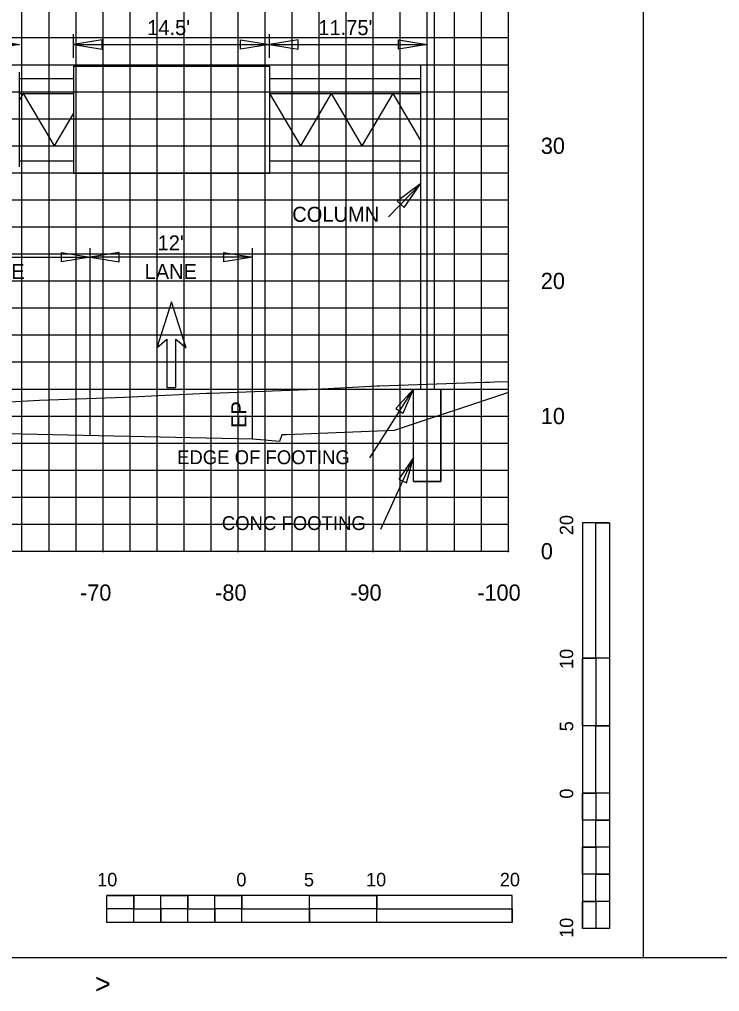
# Model space of a CAD drawing. Extents: x 2193008 to 2198143, y 1236112 to 1237864.
# Drawn here: x 2194986.7 to 2195038.5, y 1237225.5 to 1237297.5 of the extents above; entities that cross this region are included whole.
import ezdxf

# ---------------------------------------------------------------- set-up
doc = ezdxf.new("R2010")
doc.units = 0
for name, color, linetype in [('10', 7, 'Continuous'), ('3', 7, 'Continuous'), ('31', 7, 'Continuous'), ('60', 7, 'Continuous'), ('CL-CNST', 7, 'Continuous'), ('GSCOLORFILL', 7, 'Continuous'), ('GSDIMS', 7, 'Continuous'), ('Level 1', 7, 'Continuous'), ('Level 28', 7, 'Continuous'), ('Level 55', 7, 'Continuous'), ('Level 62', 7, 'Continuous'), ('M-ROADS', 7, 'Continuous'), ('V7Level1', 7, 'Continuous')]:
    doc.layers.add(name, color=color, linetype=linetype)

msp = doc.modelspace()

# ---------------------------------------------------------------- linework, layer by layer
msp.add_line((2195016.86, 1237292.389), (2195016.86, 1237297.403))
at = {"layer": '3'}
for p, q in [((2195032.86, 1237228.046), (2195032.86, 1237323.046)), ((2195017.36, 1237306.728), (2195017.36, 1237294.084)), ((2195016.36, 1237294.084), (2195016.36, 1237270.106)), ((2195017.36, 1237294.084), (2195017.36, 1237270.106)), ((2195013.991, 1237282.842), (2195016.36, 1237285.285)), ((2194991.918, 1237266.649), (2194991.918, 1237280.525)), ((2195003.918, 1237266.385), (2195003.918, 1237280.525)), ((2195012.608, 1237265.025), (2195015.836, 1237270.106)), ((2195015.836, 1237270.106), (2195017.86, 1237270.106)), ((2195015.836, 1237263.254), (2195015.836, 1237270.106)), ((2195017.86, 1237263.254), (2195017.86, 1237270.106)), ((2195013.41, 1237259.743), (2195015.836, 1237265.045)), ((2195015.836, 1237263.254), (2195017.86, 1237263.254)), ((2194882.86, 1237228.046), (2195182.86, 1237228.046))]:
    msp.add_line(p, q, dxfattribs=at)
at = {"layer": '60'}
for p, q in [((2195022.86, 1237258.106), (2195022.86, 1237318.106)), ((2195022.92, 1237288.106), (2195022.86, 1237288.106)), ((2195022.92, 1237278.106), (2195022.86, 1237278.106)), ((2195022.92, 1237268.106), (2195022.86, 1237268.106)), ((2194892.86, 1237258.106), (2195022.86, 1237258.106)), ((2194992.86, 1237258.046), (2194992.86, 1237258.106)), ((2195002.86, 1237258.046), (2195002.86, 1237258.106)), ((2195012.86, 1237258.046), (2195012.86, 1237258.106)), ((2195022.86, 1237258.046), (2195022.86, 1237258.106)), ((2195022.92, 1237258.106), (2195022.86, 1237258.106))]:
    msp.add_line(p, q, dxfattribs=at)
at = {"layer": 'CL-CNST'}
msp.add_lwpolyline([(2195022.86, 1237269.861), (2195014.414, 1237267.045), (2195010.113, 1237266.873), (2195006.414, 1237266.725), (2195006.088, 1237266.725), (2195006.085, 1237266.725), (2195005.918, 1237266.225), (2195004.805, 1237266.314), (2195003.918, 1237266.385), (2194951.493, 1237267.538), (2194950.59, 1237267.558), (2194949.493, 1237267.582), (2194949.323, 1237268.082), (2194948.993, 1237268.082), (2194943.692, 1237268.294), (2194938.236, 1237268.512), (2194935.061, 1237268.561), (2194927.574, 1237268.677)], dxfattribs=at)
at = {"layer": 'GSCOLORFILL'}
msp.add_line((2194986.672, 1237286.538), (2194986.672, 1237293.547), dxfattribs=at)
at = {"layer": 'GSDIMS'}
for p, q in [((2194990.664, 1237294.621), (2194990.664, 1237296.362)), ((2195005.172, 1237294.621), (2195005.172, 1237296.362)), ((2194956.664, 1237295.604), (2194986.672, 1237295.604)), ((2194990.664, 1237295.604), (2195005.172, 1237295.604)), ((2195005.172, 1237295.604), (2195016.86, 1237295.604)), ((2194990.664, 1237294.001), (2195005.172, 1237294.001)), ((2194990.664, 1237294.001), (2194990.664, 1237286.084)), ((2195005.172, 1237294.001), (2195005.172, 1237286.084)), ((2195016.36, 1237294.084), (2195017.36, 1237294.084)), ((2194986.672, 1237293.084), (2194990.664, 1237293.084)), ((2195005.172, 1237293.084), (2195016.36, 1237293.084)), ((2194986.96, 1237291.974), (2194986.672, 1237291.486)), ((2194986.672, 1237291.974), (2194990.664, 1237291.974)), ((2194986.96, 1237291.974), (2194989.238, 1237288.111)), ((2195005.188, 1237291.974), (2195005.172, 1237291.946)), ((2195005.172, 1237291.974), (2195016.36, 1237291.974)), ((2195005.188, 1237291.974), (2195007.467, 1237288.111)), ((2195009.745, 1237291.974), (2195007.467, 1237288.111)), ((2195009.745, 1237291.974), (2195012.024, 1237288.111)), ((2195014.303, 1237291.974), (2195012.024, 1237288.111)), ((2195014.303, 1237291.974), (2195016.36, 1237288.485)), ((2194990.664, 1237290.527), (2194989.238, 1237288.111)), ((2194986.672, 1237288.111), (2194990.664, 1237288.111)), ((2195005.172, 1237288.111), (2195016.36, 1237288.111)), ((2194986.672, 1237287.001), (2194990.664, 1237287.001)), ((2195005.172, 1237287.001), (2195016.36, 1237287.001)), ((2194990.664, 1237286.084), (2195005.172, 1237286.084)), ((2194978.418, 1237279.864), (2194991.918, 1237279.864)), ((2195003.918, 1237279.863), (2194991.918, 1237279.863))]:
    msp.add_line(p, q, dxfattribs=at)
for points in [[(2194986.672, 1237295.604), (2194984.544, 1237295.257), (2194984.544, 1237295.952)], [(2194990.664, 1237295.604), (2194992.792, 1237295.257), (2194992.792, 1237295.952)], [(2195005.172, 1237295.604), (2195003.044, 1237295.257), (2195003.044, 1237295.952)], [(2195005.172, 1237295.604), (2195007.301, 1237295.257), (2195007.301, 1237295.952)], [(2195016.86, 1237295.604), (2195014.732, 1237295.257), (2195014.732, 1237295.952)], [(2195016.36, 1237285.285), (2195014.638, 1237284.014), (2195015.152, 1237283.535)], [(2194991.918, 1237279.864), (2194989.79, 1237279.517), (2194989.79, 1237280.211)], [(2194991.918, 1237279.863), (2194994.046, 1237279.516), (2194994.046, 1237280.21)], [(2195003.918, 1237279.863), (2195001.79, 1237279.516), (2195001.79, 1237280.21)], [(2195015.836, 1237270.106), (2195014.535, 1237268.655), (2195015.076, 1237268.312)], [(2195015.836, 1237265.045), (2195014.745, 1237263.431), (2195015.327, 1237263.164)]]:
    msp.add_lwpolyline(points, close=True, dxfattribs=at)
at = {"layer": 'Level 1'}
for p, q in [((2195028.332, 1237260.195), (2195028.332, 1237230.195)), ((2195030.332, 1237260.195), (2195028.332, 1237260.195)), ((2195030.332, 1237260.195), (2195030.332, 1237250.195)), ((2195030.332, 1237260.195), (2195030.332, 1237230.195)), ((2195029.332, 1237250.195), (2195028.332, 1237250.195)), ((2195030.332, 1237250.195), (2195028.332, 1237250.195)), ((2195029.332, 1237250.195), (2195029.332, 1237245.195)), ((2195030.332, 1237245.195), (2195028.332, 1237245.195)), ((2195030.332, 1237245.195), (2195029.332, 1237245.195)), ((2195030.332, 1237245.195), (2195030.332, 1237240.195)), ((2195029.332, 1237240.195), (2195028.332, 1237240.195)), ((2195030.332, 1237240.195), (2195028.332, 1237240.195)), ((2195029.332, 1237240.195), (2195029.332, 1237238.195)), ((2195030.332, 1237238.195), (2195029.332, 1237238.195)), ((2195030.332, 1237238.195), (2195030.332, 1237236.195)), ((2195029.332, 1237236.195), (2195028.332, 1237236.195)), ((2195029.332, 1237236.195), (2195029.332, 1237234.195)), ((2195030.332, 1237234.195), (2195029.332, 1237234.195)), ((2195030.332, 1237234.195), (2195030.332, 1237232.195)), ((2195023.128, 1237232.63), (2194993.128, 1237232.63)), ((2194993.128, 1237230.63), (2194993.128, 1237232.63)), ((2194995.128, 1237231.63), (2194995.128, 1237232.63)), ((2194999.128, 1237231.63), (2194999.128, 1237232.63)), ((2195003.128, 1237231.63), (2195003.128, 1237232.63)), ((2195003.128, 1237230.63), (2195003.128, 1237232.63)), ((2195008.128, 1237230.63), (2195008.128, 1237232.63)), ((2195013.128, 1237231.63), (2195013.128, 1237232.63)), ((2195013.128, 1237230.63), (2195013.128, 1237232.63)), ((2195023.128, 1237230.63), (2195023.128, 1237232.63)), ((2195029.332, 1237232.195), (2195028.332, 1237232.195)), ((2195029.332, 1237232.195), (2195029.332, 1237230.195)), ((2194995.128, 1237231.63), (2194993.128, 1237231.63)), ((2194997.128, 1237230.63), (2194997.128, 1237231.63)), ((2194999.128, 1237231.63), (2194997.128, 1237231.63)), ((2195001.128, 1237230.63), (2195001.128, 1237231.63)), ((2195003.128, 1237231.63), (2195001.128, 1237231.63)), ((2195008.128, 1237230.63), (2195008.128, 1237231.63)), ((2195013.128, 1237231.63), (2195008.128, 1237231.63)), ((2195023.128, 1237230.63), (2194993.128, 1237230.63)), ((2194997.128, 1237230.63), (2194995.128, 1237230.63)), ((2195001.128, 1237230.63), (2194999.128, 1237230.63)), ((2195008.128, 1237230.63), (2195003.128, 1237230.63)), ((2195023.128, 1237230.63), (2195013.128, 1237230.63)), ((2195030.332, 1237230.195), (2195028.332, 1237230.195))]:
    msp.add_line(p, q, dxfattribs=at)
for points in [[(2195029.332, 1237250.195), (2195029.332, 1237260.195), (2195030.332, 1237260.195), (2195030.332, 1237250.195)], [(2195028.332, 1237245.195), (2195028.332, 1237250.195), (2195029.332, 1237250.195), (2195029.332, 1237245.195)], [(2195029.332, 1237240.195), (2195029.332, 1237245.195), (2195030.332, 1237245.195), (2195030.332, 1237240.195)], [(2195028.332, 1237238.195), (2195028.332, 1237240.195), (2195029.332, 1237240.195), (2195029.332, 1237238.195)], [(2195029.332, 1237236.195), (2195029.332, 1237238.195), (2195030.332, 1237238.195), (2195030.332, 1237236.195)], [(2195028.332, 1237234.195), (2195028.332, 1237236.195), (2195029.332, 1237236.195), (2195029.332, 1237234.195)], [(2195029.332, 1237232.195), (2195029.332, 1237234.195), (2195030.332, 1237234.195), (2195030.332, 1237232.195)], [(2194993.128, 1237232.63), (2194995.128, 1237232.63), (2194995.128, 1237231.63), (2194993.128, 1237231.63)], [(2194997.128, 1237232.63), (2194999.128, 1237232.63), (2194999.128, 1237231.63), (2194997.128, 1237231.63)], [(2195001.128, 1237232.63), (2195003.128, 1237232.63), (2195003.128, 1237231.63), (2195001.128, 1237231.63)], [(2195008.128, 1237232.63), (2195013.128, 1237232.63), (2195013.128, 1237231.63), (2195008.128, 1237231.63)], [(2195028.332, 1237230.195), (2195028.332, 1237232.195), (2195029.332, 1237232.195), (2195029.332, 1237230.195)], [(2194995.128, 1237231.63), (2194997.128, 1237231.63), (2194997.128, 1237230.63), (2194995.128, 1237230.63)], [(2194999.128, 1237231.63), (2195001.128, 1237231.63), (2195001.128, 1237230.63), (2194999.128, 1237230.63)], [(2195003.128, 1237231.63), (2195008.128, 1237231.63), (2195008.128, 1237230.63), (2195003.128, 1237230.63)], [(2195013.128, 1237231.63), (2195023.128, 1237231.63), (2195023.128, 1237230.63), (2195013.128, 1237230.63)]]:
    msp.add_lwpolyline(points, close=True, dxfattribs=at)
at = {"layer": 'Level 28'}
for p, q in [((2194997.918, 1237276.553), (2194996.829, 1237273.155)), ((2194999.007, 1237273.155), (2194997.918, 1237276.553)), ((2194996.829, 1237273.155), (2194997.591, 1237273.795)), ((2194997.591, 1237273.795), (2194997.591, 1237270.223)), ((2194998.245, 1237270.223), (2194998.245, 1237273.795)), ((2194998.245, 1237273.795), (2194999.007, 1237273.155)), ((2194997.591, 1237270.223), (2194998.245, 1237270.223))]:
    msp.add_line(p, q, dxfattribs=at)
at = {"layer": 'Level 62'}
for p, q in [((2194986.86, 1237258.106), (2194986.86, 1237318.106)), ((2194988.86, 1237258.106), (2194988.86, 1237318.106)), ((2194990.86, 1237258.106), (2194990.86, 1237318.106)), ((2194992.86, 1237258.106), (2194992.86, 1237318.106)), ((2194994.86, 1237258.106), (2194994.86, 1237318.106)), ((2194996.86, 1237258.106), (2194996.86, 1237318.106)), ((2194998.86, 1237258.106), (2194998.86, 1237318.106)), ((2195000.86, 1237258.106), (2195000.86, 1237318.106)), ((2195002.86, 1237258.106), (2195002.86, 1237318.106)), ((2195004.86, 1237258.106), (2195004.86, 1237318.106)), ((2195006.86, 1237258.106), (2195006.86, 1237318.106)), ((2195008.86, 1237258.106), (2195008.86, 1237318.106)), ((2195010.86, 1237258.106), (2195010.86, 1237318.106)), ((2195012.86, 1237258.106), (2195012.86, 1237318.106)), ((2195014.86, 1237258.106), (2195014.86, 1237318.106)), ((2195016.86, 1237258.106), (2195016.86, 1237318.106)), ((2195018.86, 1237258.106), (2195018.86, 1237318.106)), ((2195020.86, 1237258.106), (2195020.86, 1237318.106)), ((2195022.86, 1237258.106), (2195022.86, 1237318.106)), ((2194892.86, 1237296.106), (2195022.86, 1237296.106)), ((2194892.86, 1237294.106), (2195022.86, 1237294.106)), ((2194892.86, 1237292.106), (2195022.86, 1237292.106)), ((2194892.86, 1237290.106), (2195022.86, 1237290.106)), ((2194892.86, 1237288.106), (2195022.86, 1237288.106)), ((2194892.86, 1237286.106), (2195022.86, 1237286.106)), ((2194892.86, 1237284.106), (2195022.86, 1237284.106)), ((2194892.86, 1237282.106), (2195022.86, 1237282.106)), ((2194892.86, 1237280.106), (2195022.86, 1237280.106)), ((2194892.86, 1237278.106), (2195022.86, 1237278.106)), ((2194892.86, 1237276.106), (2195022.86, 1237276.106)), ((2194892.86, 1237274.106), (2195022.86, 1237274.106)), ((2194892.86, 1237272.106), (2195022.86, 1237272.106)), ((2194892.86, 1237270.106), (2195022.86, 1237270.106)), ((2194892.86, 1237268.106), (2195022.86, 1237268.106)), ((2194892.86, 1237266.106), (2195022.86, 1237266.106)), ((2194892.86, 1237264.106), (2195022.86, 1237264.106)), ((2194892.86, 1237262.106), (2195022.86, 1237262.106)), ((2194892.86, 1237260.106), (2195022.86, 1237260.106)), ((2194892.86, 1237258.106), (2195022.86, 1237258.106))]:
    msp.add_line(p, q, dxfattribs=at)
at = {"layer": 'M-ROADS'}
msp.add_lwpolyline([(2195022.86, 1237270.65), (2195021.824, 1237270.613), (2195021.475, 1237270.601), (2195021.109, 1237270.588), (2195013.318, 1237270.311), (2195013.154, 1237270.314), (2195008.612, 1237270.079), (2195000.898, 1237269.781), (2195000.523, 1237269.781), (2194994.46, 1237269.473), (2194988.149, 1237269.261), (2194983.709, 1237269.009)], dxfattribs=at)
at = {"layer": 'V7Level1'}
msp.add_lwpolyline([(2195017.86, 1237263.254), (2195015.836, 1237263.254), (2195015.836, 1237270.106), (2195017.86, 1237270.106)], close=True, dxfattribs=at)

# ---------------------------------------------------------------- texts
at = {"layer": '10'}
for s, p in [('-70', (2194991.157, 1237254.446)), ('-80', (2195001.157, 1237254.446)), ('-90', (2195011.157, 1237254.446)), ('-100', (2195020.557, 1237254.446))]:
    msp.add_text(s, height=1.2, dxfattribs=at).set_placement(p)
at = {"layer": '31'}
for s, p in [('30', (2195025.26, 1237287.506)), ('20', (2195025.26, 1237277.506)), ('10', (2195025.26, 1237267.506)), ('0', (2195025.26, 1237257.506))]:
    msp.add_text(s, height=1.2, dxfattribs=at).set_placement(p)
at = {"layer": '60'}
msp.add_text('>', height=1.5, dxfattribs=at).set_placement((2194992.252, 1237225.356))
at = {"layer": 'Level 1'}
for s, height, rotation, p in [('20', 0.9991, 90.0572, (2195027.658, 1237259.295)), ('10', 0.9991, 90.0572, (2195027.658, 1237249.395)), ('5', 1, 90.0572, (2195027.658, 1237244.78)), ('0', 1, 90.0572, (2195027.658, 1237239.795)), ('10', 0.9991, 0.0572, (2194992.428, 1237233.305)), ('0', 1, 0.0572, (2195002.728, 1237233.304)), ('5', 0.999, 0.0572, (2195007.729, 1237233.304)), ('10', 0.9991, 0.0572, (2195012.328, 1237233.305)), ('20', 0.9991, 0.0572, (2195022.229, 1237233.305)), ('10', 0.9991, 90.0572, (2195027.658, 1237229.495))]:
    msp.add_text(s, height=height, rotation=rotation, dxfattribs=at).set_placement(p)
at = {"layer": 'Level 55'}
for s, height, p in [("14.5'", 1.1105, (2194996.125, 1237296.293)), ("11.75'", 1.1105, (2195008.792, 1237296.293)), ('COLUMN', 1.1105, (2195006.864, 1237282.479)), ("12'", 1.1105, (2194996.897, 1237280.363)), ('LANE', 1.1105, (2194983.182, 1237278.254)), ('LANE', 1.1105, (2194995.932, 1237278.252)), ('EDGE OF FOOTING', 1.02464, (2194998.337, 1237264.546)), ('CONC FOOTING', 1.02464, (2195001.651, 1237259.673))]:
    msp.add_text(s, height=height, dxfattribs=at).set_placement(p)
msp.add_text('EP', height=1.1105, rotation=90, dxfattribs=at).set_placement((2195003.466, 1237267.222))

doc.saveas('drawing.dxf')
